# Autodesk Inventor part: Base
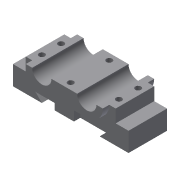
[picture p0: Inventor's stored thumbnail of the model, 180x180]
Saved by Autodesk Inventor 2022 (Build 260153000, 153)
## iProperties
Created: 2002-02
Part Number: Base
Document SubType Name: Modeling
Designer: ***
Density: 1 g/cm^3
Material: Generic
Appearance: Default
Control State: 0
Master: False
Checked Out: False
Shininess: 77.0
Length Units: 11269
Angle Units: 11279
Time Units: 11290
Mass Units: 11283
Length Display Precision: 3
Angle Display Precision: 2
Density: 0.0
Volumn: 0.0
Area: 0.0
PropertySet Name: Model Information
Author: ***
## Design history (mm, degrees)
sketch "Sketch2"
  geometry: L1 (-10.066, -1.263)-(24.934, -1.263); L2 (37.434, 11.237)-(32.434, 11.237); L3 (17.434, 11.237)-(-2.566, 11.237); L4 (-17.566, 11.237)-(-22.566, 11.237); A1 r 12.5 centre (-10.066, 11.237) between (-22.566, 11.237) and (-10.066, -1.263); A2 r 12.5 centre (24.934, 11.237) between (24.934, -1.263) and (37.434, 11.237); A3 r 7.5 centre (24.934, 11.237) between (17.434, 11.237) and (32.434, 11.237); A4 r 7.5 centre (-10.066, 11.237) between (-17.566, 11.237) and (-2.566, 11.237)
  constraints: 8 end point, 8 point on circle, 4 centre point, 3 horizontal, 3 parallel, 2 coincident, 2 equal radius, 2 tangent
  dimensions: "d0" = 12.5 radius of A1; "d1" = 7.5 radius of A4; "d2" = 35 distance of A1.centre A2.centre; "d3" = 12.5 distance between parallel lines of L3 L1
extrude "Extrusion1" new body sketch "Sketch2" stored distance "d4" = 40; taper "d5" = 0 deg
sketch "Sketch4"
  geometry: L1 (-27.566, 1.237)-(-37.566, 1.237); L2 (-37.566, 1.237)-(-37.566, -13.763); L3 (-37.566, -13.763)-(-15.066, -13.763); L4 (-15.066, -13.763)-(-20.066, -8.763); L5 (-20.066, -8.763)-(34.934, -8.763); L6 (34.934, -8.763)-(29.934, -13.763); L7 (29.934, -13.763)-(52.434, -13.763); L8 (52.434, -13.763)-(52.434, 1.237); L9 (52.434, 1.237)-(42.434, 1.237); L10 (24.934, -1.263)-(-10.066, -1.263); L11 (-17.566, 11.237)-(-22.566, 11.237) reference; L12 (37.434, 11.237)-(32.434, 11.237) reference; L13 (-22.566, 11.237)-(-27.566, 11.237); L14 (-27.566, 11.237)-(-27.566, 1.237); L15 (37.434, 11.237)-(42.434, 11.237); L16 (42.434, 11.237)-(42.434, 1.237); A1 r 12.5 centre (24.934, 11.237) between (24.934, -1.263) and (37.434, 11.237); A2 r 12.5 centre (-10.066, 11.237) between (-22.566, 11.237) and (-10.066, -1.263); A3 r 12.5 centre (24.934, 11.237) between (24.934, -1.263) and (37.434, 11.237) reference; A4 r 12.5 centre (-10.066, 11.237) between (-22.566, 11.237) and (-10.066, -1.263) reference
  constraints: 28 end point, 6 perpendicular, 5 equal length, 4 concentric, 4 parallel, 4 point on circle, 2 centre point, 2 collinear, 1 tangent
  dimensions: "d12" = 15 distance of L1.end L2.end; "d13" = 25 distance from line of L3 L11.end; "d14" = 90 distance between parallel lines of L2 L8; "d15" = 5 distance between parallel lines of L5 L7; "d16" = 22.5 distance of L2.end L3.end; "d24" = 5 distance of L12.start L15.end; "d25" = 15 distance from line of L8 L12.start
extrude "Extrusion3" join sketch "Sketch4" stored distance "d17" = 30; taper "d18" = 0 deg
sketch "Sketch5"
  geometry: L1 (-14.934, -1.263)-(0.066, -1.263); L2 (0.066, -1.263)-(0.066, -8.763); L3 (0.066, -8.763)-(-14.934, -8.763); L4 (-14.934, -8.763)-(-14.934, -1.263); L5 (10.066, -1.263)-(-24.934, -1.263) reference; 1 further point
  constraints: 8 end point, 2 parallel, 1 collinear, 1 horizontal, 1 perpendicular
  dimensions: "d19" = 7.5 distance of L1.end L2.end; "d20" = 15 distance of L2.end L3.end; "d21" = 15 distance from line of point (-29.934, -13.763) L4
extrude "Extrusion4" join sketch "Sketch5" distance "d22" = 40; taper "d23" = 0 deg
sketch "Sketch6"
  geometry: L1 (-5, -35)-(0, -35) reference; L2 (-5, -35)-(-5, -5) reference; 1 further point
  dimensions: "d26" = 7.5 distance from line of L1 point (0, -27.5); "d27" = 5 distance from line of L2 point (0, -27.5)
hole "Hole1" sketch "Sketch6" at (0, -27.5) diameter "d28" = 4.5; stored, may be unused: countersink angle "d32" = 82 deg, drill point angle "d34" = 0 deg; dims "d29" = 6, "d30" = 4, "d31" = 2, "d33" = 15
pattern_linear "Rectangular Pattern1" dims "d37" = 60, "d40" = 15
sketch "Sketch7"
  geometry: L1 (-20, -40)-(-20, -35) reference; L2 (0, -40)-(20, -40) reference; 1 further point
  dimensions: "d41" = 30 distance from line of L1 point (10, -35); "d42" = 5 distance from line of L2 point (10, -35)
hole "Hole2" sketch "Sketch7" at (10, -35) diameter "d43" = 4.5; stored, may be unused: countersink angle "d47" = 82 deg, drill point angle "d49" = 0 deg; dims "d44" = 6, "d45" = 4, "d46" = 2, "d48" = 15
pattern_linear "Rectangular Pattern2" dims "d52" = 30
body "Solid1"
